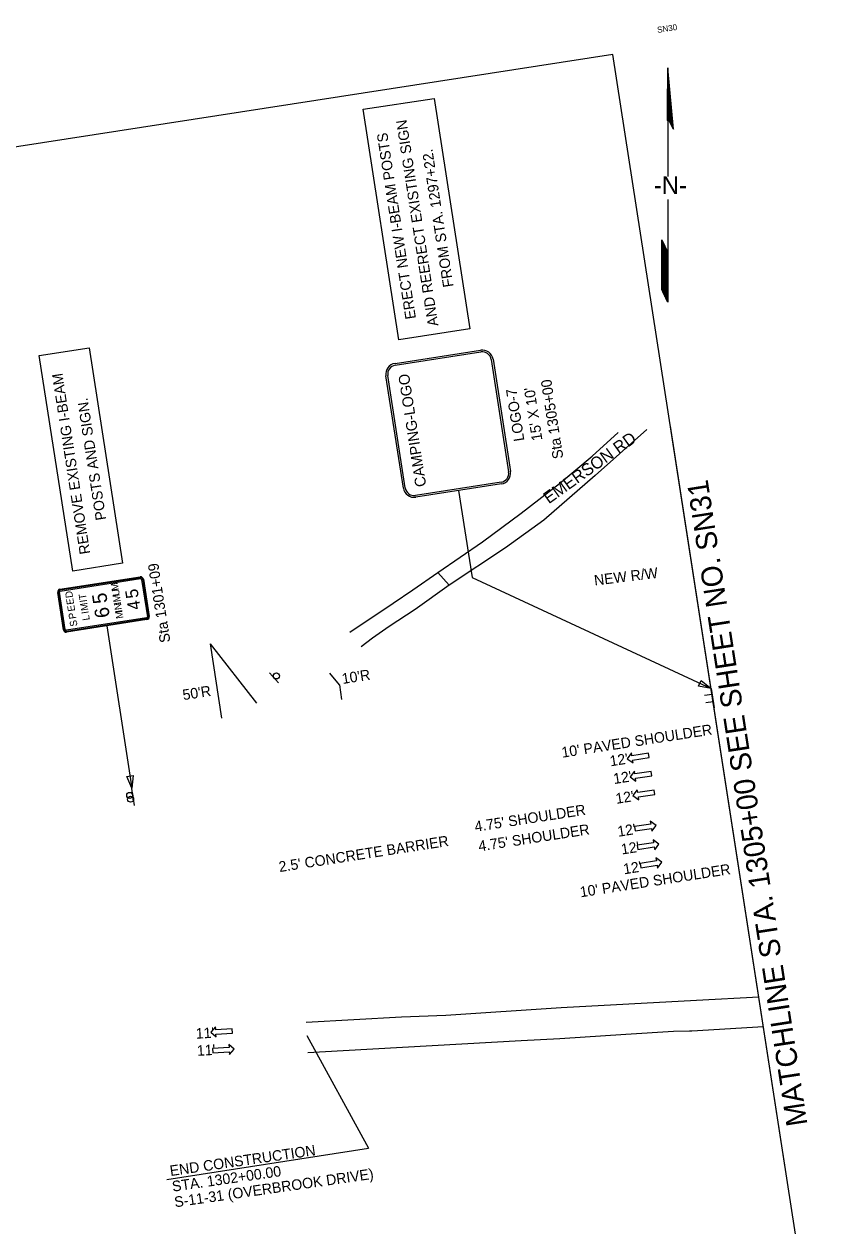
# Model space of a CAD drawing. Extents: x 1778251 to 1779871, y 1179849 to 1181087.
# Drawn here: x 1779342 to 1779871, y 1180288 to 1181087 of the extents above; entities that cross this region are included whole.
import ezdxf

# ---------------------------------------------------------------- set-up
doc = ezdxf.new("R2010")
doc.units = 0
for name, color, linetype in [('RD_EX_BldgApp', 7, 'Continuous'), ('RD_EX_Road', 7, 'Continuous'), ('RD_HC_Data', 7, 'Continuous'), ('RD_PD_FOC', 7, 'Continuous'), ('RD_PD_GR', 7, 'Continuous'), ('RD_PD_PatLn1', 7, 'Continuous'), ('RD_PD_PaveShd', 7, 'Continuous'), ('RD_SHT_MatchLine', 7, 'Continuous'), ('RD_Sketch1', 7, 'Continuous'), ('RD_Sketch2', 7, 'Continuous'), ('RD_TX_RoadID', 7, 'Continuous')]:
    doc.layers.add(name, color=color, linetype=linetype)

# ---------------------------------------------------------------- blocks, each defined once
blk = doc.blocks.new('NA5')
at = {"layer": 'RD_Sketch1'}
for p, q in [((26.81, 30.64), (47.48, 65.89)), ((47.48, 65.89), (26.84, 37.43)), ((27.18, 37.55), (14.47, 19.81)), ((28.07, 38.27), (26.81, 30.64)), ((14.47, 19.81), (5.46, 7.23)), ((-3.53, -5.33), (-18.54, -26.28)), ((-18.54, -26.28), (-43.3, -60.85)), ((-30.56, -36.2), (-22.3, -24.68)), ((-22.3, -24.68), (-24.05, -33.97)), ((-41.56, -51.56), (-30.56, -36.2)), ((-43.3, -60.85), (-41.56, -51.56))]:
    blk.add_line(p, q, dxfattribs=at)
for points in [[(27.37, 37.79), (47.42, 65.79)], [(27.6, 37.95), (46.9, 64.9)], [(27.82, 38.1), (46.37, 64)], [(27.8, 36.6), (41.65, 55.95)], [(27.83, 36.82), (42.18, 56.85)], [(27.86, 37.03), (42.7, 57.74)], [(27.9, 37.24), (43.23, 58.63)], [(27.93, 37.45), (43.75, 59.53)], [(27.97, 37.66), (44.28, 60.42)], [(28, 37.87), (44.8, 61.32)], [(28.04, 38.08), (45.32, 62.21)], [(28.05, 38.26), (45.85, 63.11)], [(27.14, 37.64), (39.24, 54.53)], [(27.52, 34.92), (37.46, 48.8)], [(27.55, 35.13), (37.98, 49.69)], [(27.59, 35.34), (38.51, 50.58)], [(27.62, 35.55), (39.03, 51.48)], [(27.66, 35.76), (39.56, 52.37)], [(27.69, 35.97), (40.08, 53.27)], [(27.73, 36.18), (40.6, 54.16)], [(27.76, 36.39), (41.13, 55.06)], [(26.91, 37.48), (29.9, 41.66)], [(27.2, 33.02), (32.74, 40.75)], [(27.24, 33.23), (33.26, 41.64)], [(27.27, 33.44), (33.79, 42.54)], [(27.31, 33.65), (34.31, 43.43)], [(27.34, 33.86), (34.84, 44.32)], [(27.38, 34.07), (35.36, 45.22)], [(27.41, 34.28), (35.88, 46.11)], [(27.45, 34.5), (36.41, 47.01)], [(27.48, 34.71), (36.93, 47.9)], [(26.89, 31.12), (28.02, 32.7)], [(26.92, 31.33), (28.54, 33.59)], [(26.96, 31.54), (29.07, 34.49)], [(26.99, 31.75), (29.59, 35.38)], [(27.03, 31.96), (30.12, 36.27)], [(27.06, 32.18), (30.64, 37.17)], [(27.1, 32.39), (31.16, 38.06)], [(27.13, 32.6), (31.69, 38.96)], [(27.17, 32.81), (32.21, 39.85)], [(26.82, 30.7), (26.97, 30.91)], [(26.85, 30.91), (27.49, 31.8)], [(-42.91, -58.77), (-23.66, -31.89)], [(-42.87, -58.55), (-23.61, -31.67)], [(-42.83, -58.34), (-23.57, -31.45)], [(-42.79, -58.12), (-23.53, -31.23)], [(-42.75, -57.9), (-23.49, -31.01)], [(-42.71, -57.68), (-23.45, -30.79)], [(-42.67, -57.46), (-23.41, -30.57)], [(-42.63, -57.24), (-23.37, -30.35)], [(-42.58, -57.02), (-23.33, -30.13)], [(-42.54, -56.8), (-23.29, -29.91)], [(-42.5, -56.58), (-23.24, -29.69)], [(-42.46, -56.36), (-23.2, -29.47)], [(-42.42, -56.14), (-23.16, -29.25)], [(-42.38, -55.92), (-23.12, -29.03)], [(-42.34, -55.7), (-23.08, -28.81)], [(-42.3, -55.48), (-23.04, -28.59)], [(-42.25, -55.26), (-23, -28.37)], [(-42.21, -55.04), (-22.96, -28.15)], [(-42.17, -54.82), (-22.91, -27.93)], [(-42.13, -54.6), (-22.87, -27.71)], [(-42.09, -54.38), (-22.83, -27.49)], [(-42.05, -54.16), (-22.79, -27.27)], [(-42.01, -53.94), (-22.75, -27.05)], [(-41.97, -53.72), (-22.71, -26.83)], [(-41.93, -53.5), (-22.67, -26.62)], [(-41.88, -53.28), (-22.63, -26.4)], [(-41.84, -53.06), (-22.59, -26.18)], [(-41.8, -52.84), (-22.54, -25.96)], [(-41.76, -52.62), (-22.5, -25.74)], [(-41.72, -52.4), (-22.46, -25.52)], [(-41.68, -52.18), (-22.42, -25.3)], [(-41.64, -51.96), (-22.38, -25.08)], [(-41.6, -51.74), (-22.34, -24.86)], [(-43.28, -60.75), (-24.03, -33.87)], [(-43.24, -60.53), (-23.99, -33.65)], [(-43.2, -60.31), (-23.94, -33.43)], [(-43.16, -60.09), (-23.9, -33.21)], [(-43.12, -59.87), (-23.86, -32.99)], [(-43.08, -59.65), (-23.82, -32.77)], [(-43.04, -59.43), (-23.78, -32.55)], [(-43, -59.21), (-23.74, -32.33)], [(-42.95, -58.99), (-23.7, -32.11)]]:
    blk.add_lwpolyline(points, dxfattribs=at)
blk.add_text('-N-', height=11.811, rotation=324.3865, dxfattribs=at).set_placement((-8.85, 3.04))
blk = doc.blocks.new('SARRW2')
at = {"layer": 'RD_Sketch2'}
blk.add_lwpolyline([(-12, 1.2), (-12, -1.2), (-2.83, -1.2), (-2.83, -2.83), (0, 0), (-2.83, 2.83), (-2.83, 1.2)], close=True, dxfattribs=at)

msp = doc.modelspace()

# ---------------------------------------------------------------- linework, layer by layer
at = {"layer": 'RD_EX_BldgApp'}
for p, q in [((1779505.4, 1180655.57), (1779511.43, 1180648.89)), ((1779415.02, 1180569.93), (1779413.92, 1180578.87)), ((1779415.66, 1180567.41), (1779414.39, 1180576.32))]:
    msp.add_line(p, q, dxfattribs=at)
for centre in [(1779509.93, 1180653.58), (1779412.46, 1180574.17), (1779413.02, 1180571.6)]:
    msp.add_circle(centre, 2, dxfattribs=at)
at = {"layer": 'RD_EX_Road'}
for points in [[(1779756.23, 1180817.32), (1779721.95, 1180786.81), (1779687.83, 1180757.15), (1779662.26, 1180738.7), (1779624.9, 1180714.02)], [(1779617.38, 1180722.3), (1779647.01, 1180742.83), (1779672.67, 1180761.88), (1779698.23, 1180781.58), (1779719.83, 1180799.73), (1779737.14, 1180815.47)], [(1779558.87, 1180682.76), (1779587.68, 1180701.96), (1779600.75, 1180710.93), (1779617.38, 1180722.3), (1779624.9, 1180714.02), (1779602.2, 1180697.75), (1779596.35, 1180694.04), (1779585, 1180686.47), (1779573.87, 1180678.58), (1779566.31, 1180672.89)], [(1779830.72, 1180439.91), (1779789.19, 1180437.79), (1779699.32, 1180432.87), (1779622.48, 1180427.9), (1779593.18, 1180426.7), (1779529.73, 1180423.09)], [(1779530.86, 1180403.28), (1779554.44, 1180404.62), (1779672.6, 1180411.07), (1779698.4, 1180412.41), (1779742.22, 1180415.3), (1779774, 1180417.4), (1779784.6, 1180417.52), (1779786.19, 1180417.54), (1779833.73, 1180420.45)]]:
    msp.add_lwpolyline(points, dxfattribs=at)
at = {"layer": 'RD_HC_Data'}
msp.add_lwpolyline([(1779870.61, 1180182.22), (1779733.69, 1181066.68), (1778251.34, 1180837.21), (1778404.33, 1179848.98), (1779093.19, 1179955.62), (1779077.13, 1180059.38)], close=True, dxfattribs=at)
at = {"layer": 'RD_PD_GR'}
for p, q in [((1779465.83, 1180674.84), (1779473.48, 1180625.43)), ((1779465.83, 1180674.84), (1779496.74, 1180635.54)), ((1779551.8, 1180647.68), (1779545.38, 1180655.35)), ((1779551.8, 1180647.68), (1779553.32, 1180637.8)), ((1779530.22, 1180414.46), (1779571.15, 1180339.57)), ((1779437.07, 1180318.81), (1779571.15, 1180339.57))]:
    msp.add_line(p, q, dxfattribs=at)
at = {"layer": 'RD_PD_PatLn1'}
for p, q in [((1779567.71, 1181030.33), (1779614.77, 1181037.61)), ((1779614.77, 1181037.61), (1779638.49, 1180884.42)), ((1779591.43, 1180877.13), (1779567.71, 1181030.33)), ((1779638.49, 1180884.42), (1779591.43, 1180877.13)), ((1779352.36, 1180866.63), (1779385.58, 1180871.77)), ((1779374.55, 1180723.32), (1779352.36, 1180866.63)), ((1779385.58, 1180871.77), (1779407.77, 1180728.46)), ((1779631.05, 1180776.82), (1779640.01, 1180718.92)), ((1779407.77, 1180728.46), (1779374.55, 1180723.32)), ((1779366.11, 1180711.19), (1779419.48, 1180719.45)), ((1779421.53, 1180717.95), (1779425.38, 1180693.05)), ((1779640.01, 1180718.92), (1779798.94, 1180645.19)), ((1779368.46, 1180684.24), (1779364.61, 1180709.14)), ((1779423.88, 1180690.99), (1779370.52, 1180682.73)), ((1779397.2, 1180686.86), (1779413.92, 1180578.87)), ((1779505.4, 1180655.57), (1779511.43, 1180648.89)), ((1779799.54, 1180641.33), (1779794.6, 1180640.57)), ((1779798.94, 1180645.19), (1779800.93, 1180632.3)), ((1779800.3, 1180636.37), (1779795.37, 1180635.61)), ((1779415.02, 1180569.93), (1779413.92, 1180578.87)), ((1779415.66, 1180567.41), (1779414.39, 1180576.32))]:
    msp.add_line(p, q, dxfattribs=at)
for points in [[(1779588.82, 1180861.35), (1779645.74, 1180870.16)], [(1779589.01, 1180860.17), (1779645.93, 1180868.98)], [(1779652.78, 1180863.97), (1779664.34, 1180789.26)], [(1779653.96, 1180864.15), (1779665.53, 1180789.44)], [(1779594.37, 1180778.42), (1779582.81, 1180853.13)], [(1779595.56, 1180778.61), (1779583.99, 1180853.32)], [(1779659.33, 1180782.41), (1779602.41, 1180773.6)], [(1779659.51, 1180781.22), (1779602.59, 1180772.41)], [(1779366.18, 1180710.75), (1779419.54, 1180719.01)], [(1779366.29, 1180710.01), (1779419.66, 1180718.27)], [(1779420.34, 1180717.77), (1779424.2, 1180692.86)], [(1779421.08, 1180717.88), (1779424.94, 1180692.98)], [(1779368.91, 1180684.3), (1779365.05, 1180709.21)], [(1779369.65, 1180684.42), (1779365.79, 1180709.32)], [(1779423.7, 1180692.18), (1779370.33, 1180683.92)], [(1779423.81, 1180691.44), (1779370.45, 1180683.18)]]:
    msp.add_lwpolyline(points, dxfattribs=at)
for points in [[(1779792.36, 1180650.5), (1779798.94, 1180645.19), (1779790.63, 1180646.78)], [(1779414.69, 1180587.29), (1779413.92, 1180578.87), (1779410.64, 1180586.66)]]:
    msp.add_lwpolyline(points, close=True, dxfattribs=at)
for centre in [(1779509.93, 1180653.58), (1779412.46, 1180574.17), (1779413.02, 1180571.6)]:
    msp.add_circle(centre, 2, dxfattribs=at)
for centre, radius, start, end in [((1779646.85, 1180863.05), 7.2, 8.80001, 98.80001), ((1779646.85, 1180863.05), 6, 8.80001, 98.80001), ((1779589.92, 1180854.24), 7.2, 98.80001, 188.80001), ((1779589.92, 1180854.24), 6, 98.80001, 188.80001), ((1779658.41, 1180788.34), 6, 278.80001, 8.80001), ((1779658.41, 1180788.34), 7.2, 278.80001, 8.80001), ((1779601.49, 1180779.53), 7.2, 188.80001, 278.80001), ((1779601.49, 1180779.53), 6, 188.80001, 278.80001), ((1779419.75, 1180717.68), 1.8, 8.80001, 98.80001), ((1779419.75, 1180717.68), 1.35, 8.80001, 98.80001), ((1779419.75, 1180717.68), 0.6, 8.80001, 98.80001), ((1779366.39, 1180709.41), 1.8, 98.80001, 188.80001), ((1779366.39, 1180709.41), 1.35, 98.80001, 188.80001), ((1779366.39, 1180709.41), 0.6, 98.80001, 188.80001), ((1779423.61, 1180692.77), 0.6, 278.80001, 8.80001), ((1779423.61, 1180692.77), 1.35, 278.80001, 8.80001), ((1779423.61, 1180692.77), 1.8, 278.80001, 8.80001), ((1779370.24, 1180684.51), 1.8, 188.80001, 278.80001), ((1779370.24, 1180684.51), 1.35, 188.80001, 278.80001), ((1779370.24, 1180684.51), 0.6, 188.80001, 278.80001)]:
    msp.add_arc(centre, radius, start, end, dxfattribs=at)
at = {"layer": 'RD_SHT_MatchLine'}
msp.add_lwpolyline([(1779848.43, 1180325.51), (1779771.93, 1180819.63)], dxfattribs=at)

# ---------------------------------------------------------------- block references
at = {"layer": 'RD_SHT_MatchLine', "rotation": 35.61349782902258}
msp.add_blockref('NA5', (1779769.87, 1180976.68), dxfattribs=at)
at = {"layer": 'RD_Sketch2'}
for p, xscale, yscale, rotation in [((1779743.2, 1180598.53), 1.2, 1.2, -171.19998882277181), ((1779745.07, 1180586.45), 1.2, 1.2, -171.19998882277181), ((1779746.99, 1180574.07), 1.2, 1.2, -171.19998882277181), ((1779762.35, 1180554.17), 1.2, 1.1999999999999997, 8.800011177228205), ((1779764.27, 1180541.78), 1.2, 1.1999999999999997, 8.800011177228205), ((1779766.14, 1180529.7), 1.2, 1.1999999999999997, 8.800011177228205), ((1779466.31, 1180416.73), 1.1999999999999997, 1.2, -176.7359618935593), ((1779481.94, 1180405.34), 1.1999999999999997, 1.1999999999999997, 3.2640381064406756)]:
    msp.add_blockref('SARRW2', p, dxfattribs=dict(at, xscale=xscale, yscale=yscale, rotation=rotation))

# ---------------------------------------------------------------- texts
at = {"layer": 'RD_PD_FOC'}
msp.add_text('NEW R/W', height=7, rotation=6.96294, dxfattribs=at).set_placement((1779721.56, 1180713.65))
at = {"layer": 'RD_PD_GR'}
for s, rotation, p in [("10'R", 8.80001, (1779554.04, 1180648.22)), ("50'R", 8.80001, (1779448.18, 1180637.44)), ("10' PAVED SHOULDER", 8.80001, (1779700.06, 1180599.17)), ("12'", 8.80001, (1779732.11, 1180593.45)), ("12'", 8.80001, (1779734.48, 1180581.65)), ("12'", 8.80001, (1779735.98, 1180568.49)), ("4.75' SHOULDER", 8.80001, (1779642.22, 1180549.9)), ("4.75' SHOULDER", 8.80001, (1779644.79, 1180536.89)), ("12'", 8.80001, (1779737.23, 1180546.6)), ("2.5' CONCRETE BARRIER", 8.80001, (1779512.09, 1180523.13)), ("12'", 8.80001, (1779739.6, 1180534.8)), ("12'", 8.80001, (1779741.09, 1180521.64)), ("10' PAVED SHOULDER", 8.80001, (1779712.28, 1180506.36)), ("11'", 3.26404, (1779456.57, 1180412.33)), ("11'", 3.26404, (1779457.31, 1180400.93)), ('END CONSTRUCTION', 8.17319, (1779439.63, 1180321.01)), ('STA. 1302+00.00', 8.17319, (1779441.12, 1180310.62)), ('S-11-31 (OVERBROOK DRIVE)', 8.17319, (1779442.62, 1180300.23))]:
    msp.add_text(s, height=7, rotation=rotation, dxfattribs=at).set_placement(p)
at = {"layer": 'RD_PD_PatLn1'}
for s, height, rotation, p in [('AND REERECT EXISTING SIGN', 6.9998, 98.80009, (1779617.65, 1180886.61)), ('ERECT NEW I-BEAM POSTS', 6.9998, 98.80009, (1779602.76, 1180891.31)), ('FROM STA. 1297+22.', 6.9998, 98.80009, (1779627.8, 1180912.55)), ('REMOVE EXISTING I-BEAM', 6.9998, 98.80009, (1779386.26, 1180734.99)), ('CAMPING-LOGO', 7.2, 98.80001, (1779609.64, 1180779.84)), ('Sta 1305+00', 7, 98.80009, (1779700.74, 1180798.44)), ('LOGO-7', 7, 98.80009, (1779674.85, 1180810.1)), ("15' X 10'", 7, 98.80009, (1779686.83, 1180810.51)), ('POSTS AND SIGN. ', 6.9998, 98.80009, (1779396.93, 1180757.6)), ('Sta 1301+09', 7, 98.80009, (1779439.54, 1180676.25)), ('M', 4.8, 98.80001, (1779405.35, 1180710.68)), ('D', 4.8, 98.80001, (1779374.84, 1180705.8)), ('E', 4.8, 98.80001, (1779375.53, 1180701.31)), ('T', 4.8, 98.80001, (1779383.81, 1180704.69)), ('5', 9.6, 98.80001, (1779397.83, 1180702.38)), ('U', 4.8, 98.80001, (1779405.91, 1180707.09)), ('M', 4.8, 98.80001, (1779406.54, 1180703.01)), ('5', 8.4, 98.80001, (1779418.55, 1180705.8)), ('E', 4.8, 98.80001, (1779376.23, 1180696.81)), ('I', 4.8, 98.80001, (1779384.09, 1180702.9)), ('M', 4.8, 98.80001, (1779384.96, 1180697.3)), ('6', 9.6, 98.80001, (1779399.31, 1180692.87)), ('I', 4.8, 98.80001, (1779406.8, 1180701.35)), ('N', 4.8, 98.80001, (1779407.35, 1180697.75)), ('I', 4.8, 98.80001, (1779407.61, 1180696.09)), ('4', 8.4, 98.80001, (1779419.74, 1180698.15)), ('P', 4.8, 98.80001, (1779377.01, 1180691.78)), ('S', 4.8, 98.80001, (1779377.79, 1180686.74)), ('I', 4.8, 98.80001, (1779385.27, 1180695.26)), ('L', 4.8, 98.80001, (1779385.96, 1180690.8)), ('M', 4.8, 98.80001, (1779408.24, 1180692.01))]:
    msp.add_text(s, height=height, rotation=rotation, dxfattribs=at).set_placement(p)
at = {"layer": 'RD_PD_PaveShd'}
msp.add_text('SN30', height=4, rotation=8.80001, dxfattribs=at).set_placement((1779763.38, 1181081.09))
at = {"layer": 'RD_SHT_MatchLine'}
msp.add_text('MATCHLINE STA. 1305+00 SEE SHEET NO. SN31', height=14, rotation=98.80001, dxfattribs=at).set_placement((1779863.04, 1180355.32))
at = {"layer": 'RD_TX_RoadID'}
msp.add_text('EMERSON RD', height=8, rotation=35.61986, dxfattribs=at).set_placement((1779691.05, 1180767.67))

doc.saveas('drawing.dxf')
